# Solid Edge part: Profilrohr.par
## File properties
Username: ahadarics
Dokumentum tartalom típus: 0
Author: ahadarics
Last saved by: ahadarics
Revision: 84
Sűrűség: 0,000 kg/m^3
Pontosság: 0,990
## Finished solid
Body 1: solid body, 6 faces, 6 edges, 0 vertices.
  Faces by surface: cone 2, cylinder 2, plane 2
  Edges by curve: circle 6
Bounding box of the edges (mm): 13.270 x 13.270 x 277.000, from (-6.635, -6.635, -258.5) to (6.635, 6.635, 18.5).
Cylindrical faces by radius (mm): R6 x1, R6.635 x1
Conical faces (half-angle, radius in mm at the cone's reference point): 15 deg R6.067 x2
Planar faces by outward normal: +z 1, -z 1
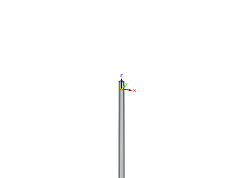
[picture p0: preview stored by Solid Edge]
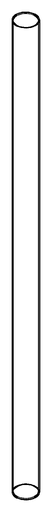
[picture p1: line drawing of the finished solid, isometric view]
